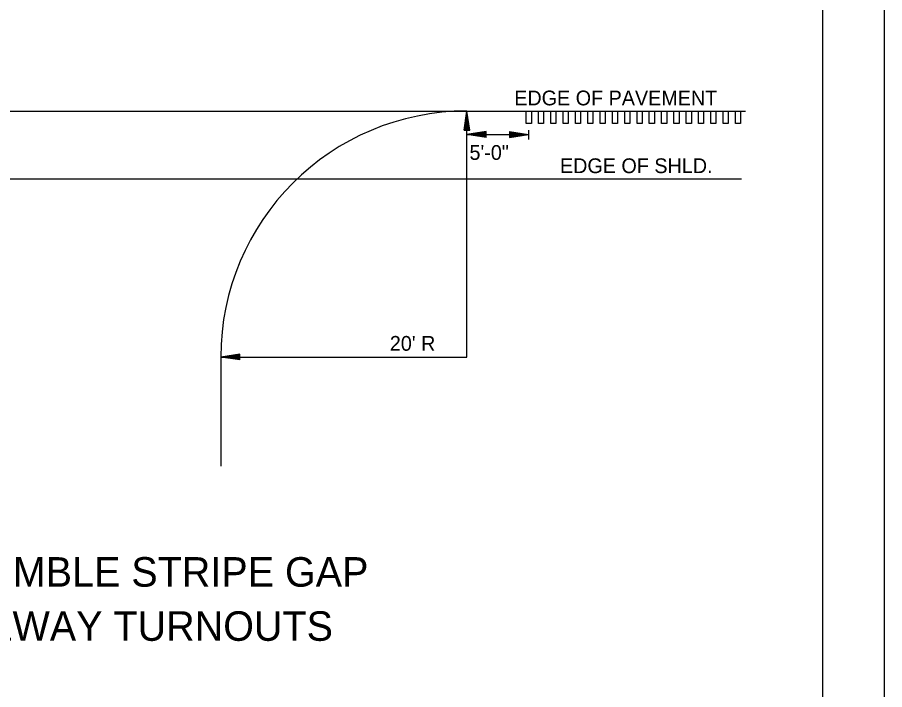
# Model space of a CAD drawing. Extents: x 1371343 to 1373043, y 378740 to 382040.
# Drawn here: x 1372692.4 to 1373042.9, y 380373.5 to 380645.4 of the extents above; entities that cross this region are included whole.
import ezdxf

# ---------------------------------------------------------------- set-up
doc = ezdxf.new("R2010")
doc.units = 0
for name, color, linetype in [('E_Existing ROW', 7, 'Continuous'), ('R_Border Notes', 7, 'Continuous'), ('R_Border PE', 7, 'Continuous')]:
    doc.layers.add(name, color=color, linetype=linetype)

msp = doc.modelspace()

# ---------------------------------------------------------------- linework, layer by layer
at = {"layer": 'E_Existing ROW'}
for points in [[(1371342.92, 379840.49), (1373042.92, 379840.49), (1373042.92, 380940.49), (1371342.92, 380940.49)], [(1371367.92, 379865.49), (1373017.92, 379865.49), (1373017.92, 380915.49), (1371367.92, 380915.49)]]:
    msp.add_lwpolyline(points, close=True, dxfattribs=at)
at = {"layer": 'R_Border Notes'}
for p, q in [((1372475.93, 380607.52), (1372986.72, 380607.52)), ((1372874.12, 380508.02), (1372874.12, 380607.52)), ((1372898.99, 380599.74), (1372898.99, 380596.06)), ((1372874.12, 380598.03), (1372898.99, 380598.03)), ((1372474.28, 380580.11), (1372985.07, 380580.11)), ((1372774.61, 380508.02), (1372774.61, 380463.96)), ((1372774.61, 380508.02), (1372874.12, 380508.02))]:
    msp.add_line(p, q, dxfattribs=at)
for points in [[(1372898.06, 380602.54), (1372898.06, 380607.51), (1372900.13, 380607.51), (1372900.13, 380602.54), (1372898.06, 380602.54)], [(1372903.03, 380602.54), (1372903.03, 380607.51), (1372905.1, 380607.51), (1372905.1, 380602.54), (1372903.03, 380602.54)], [(1372908.01, 380602.54), (1372908.01, 380607.51), (1372910.08, 380607.51), (1372910.08, 380602.54), (1372908.01, 380602.54)], [(1372912.98, 380602.54), (1372912.98, 380607.51), (1372915.05, 380607.51), (1372915.05, 380602.54), (1372912.98, 380602.54)], [(1372917.95, 380602.54), (1372917.95, 380607.51), (1372920.03, 380607.51), (1372920.03, 380602.54), (1372917.95, 380602.54)], [(1372922.93, 380602.54), (1372922.93, 380607.51), (1372925, 380607.51), (1372925, 380602.54), (1372922.93, 380602.54)], [(1372927.9, 380602.54), (1372927.9, 380607.51), (1372929.98, 380607.51), (1372929.98, 380602.54), (1372927.9, 380602.54)], [(1372932.88, 380602.54), (1372932.88, 380607.51), (1372934.95, 380607.51), (1372934.95, 380602.54), (1372932.88, 380602.54)], [(1372937.85, 380602.54), (1372937.85, 380607.51), (1372939.93, 380607.51), (1372939.93, 380602.54), (1372937.85, 380602.54)], [(1372942.83, 380602.54), (1372942.83, 380607.51), (1372944.9, 380607.51), (1372944.9, 380602.54), (1372942.83, 380602.54)], [(1372947.8, 380602.54), (1372947.8, 380607.51), (1372949.88, 380607.51), (1372949.88, 380602.54), (1372947.8, 380602.54)], [(1372952.78, 380602.54), (1372952.78, 380607.51), (1372954.85, 380607.51), (1372954.85, 380602.54), (1372952.78, 380602.54)], [(1372957.75, 380602.54), (1372957.75, 380607.51), (1372959.82, 380607.51), (1372959.82, 380602.54), (1372957.75, 380602.54)], [(1372962.73, 380602.54), (1372962.73, 380607.51), (1372964.8, 380607.51), (1372964.8, 380602.54), (1372962.73, 380602.54)], [(1372967.7, 380602.54), (1372967.7, 380607.51), (1372969.77, 380607.51), (1372969.77, 380602.54), (1372967.7, 380602.54)], [(1372972.68, 380602.54), (1372972.68, 380607.51), (1372974.75, 380607.51), (1372974.75, 380602.54), (1372972.68, 380602.54)], [(1372977.65, 380602.54), (1372977.65, 380607.51), (1372979.72, 380607.51), (1372979.72, 380602.54), (1372977.65, 380602.54)], [(1372982.63, 380602.54), (1372982.63, 380607.51), (1372984.7, 380607.51), (1372984.7, 380602.54), (1372982.63, 380602.54)]]:
    msp.add_lwpolyline(points, dxfattribs=at)
msp.add_arc((1372874.12, 380508.02), 99.51, 90, 180, dxfattribs=at)
at = {"layer": 'R_Border PE'}
for p, q in [((1372872.97, 380599.82), (1372874.12, 380607.52)), ((1372872.97, 380599.82), (1372874.12, 380607.52)), ((1372875.28, 380599.82), (1372874.12, 380607.52)), ((1372875.28, 380599.82), (1372874.12, 380607.52)), ((1372873.16, 380599.82), (1372874.12, 380606.24)), ((1372873.16, 380599.82), (1372874.12, 380606.24)), ((1372873.35, 380599.82), (1372874.12, 380604.91)), ((1372873.35, 380599.82), (1372874.12, 380604.91)), ((1372873.55, 380599.82), (1372874.12, 380603.63)), ((1372873.55, 380599.82), (1372874.12, 380603.63)), ((1372875.08, 380599.82), (1372874.12, 380606.24)), ((1372875.08, 380599.82), (1372874.12, 380606.24)), ((1372874.89, 380599.82), (1372874.12, 380604.91)), ((1372874.89, 380599.82), (1372874.12, 380604.91)), ((1372874.69, 380599.82), (1372874.12, 380603.63)), ((1372874.69, 380599.82), (1372874.12, 380603.63)), ((1372872.97, 380599.82), (1372875.28, 380599.82)), ((1372872.97, 380599.82), (1372875.28, 380599.82)), ((1372873.75, 380599.82), (1372874.12, 380602.32)), ((1372873.75, 380599.82), (1372874.12, 380602.32)), ((1372873.94, 380599.82), (1372874.12, 380601.04)), ((1372873.94, 380599.82), (1372874.12, 380601.04)), ((1372874.5, 380599.82), (1372874.12, 380602.32)), ((1372874.5, 380599.82), (1372874.12, 380602.32)), ((1372874.3, 380599.82), (1372874.12, 380601.04)), ((1372874.3, 380599.82), (1372874.12, 380601.04)), ((1372881.83, 380599.19), (1372874.12, 380598.03)), ((1372881.83, 380596.87), (1372874.12, 380598.03)), ((1372881.83, 380598.99), (1372875.41, 380598.03)), ((1372881.83, 380597.07), (1372875.41, 380598.03)), ((1372881.83, 380598.8), (1372876.73, 380598.03)), ((1372881.83, 380597.26), (1372876.73, 380598.03)), ((1372881.83, 380598.6), (1372878.02, 380598.03)), ((1372881.83, 380597.46), (1372878.02, 380598.03)), ((1372881.83, 380598.41), (1372879.32, 380598.03)), ((1372881.83, 380597.66), (1372879.32, 380598.03)), ((1372881.83, 380598.21), (1372880.61, 380598.03)), ((1372881.83, 380597.85), (1372880.61, 380598.03)), ((1372881.83, 380596.87), (1372881.83, 380599.19)), ((1372891.29, 380599.19), (1372898.99, 380598.03)), ((1372891.29, 380599.19), (1372891.29, 380596.87)), ((1372891.29, 380598.99), (1372897.71, 380598.03)), ((1372891.29, 380598.8), (1372896.38, 380598.03)), ((1372891.29, 380598.6), (1372895.1, 380598.03)), ((1372891.29, 380598.4), (1372893.79, 380598.03)), ((1372891.29, 380598.21), (1372892.51, 380598.03)), ((1372891.29, 380596.87), (1372898.99, 380598.03)), ((1372891.29, 380597.65), (1372893.79, 380598.03)), ((1372891.29, 380597.26), (1372896.38, 380598.03)), ((1372891.29, 380597.07), (1372897.71, 380598.03)), ((1372891.29, 380597.46), (1372895.1, 380598.03)), ((1372891.29, 380597.85), (1372892.51, 380598.03)), ((1372782.32, 380509.17), (1372774.61, 380508.02)), ((1372782.32, 380509.17), (1372774.61, 380508.02)), ((1372782.32, 380508.98), (1372775.9, 380508.02)), ((1372782.32, 380508.98), (1372775.9, 380508.02)), ((1372782.32, 380508.78), (1372777.23, 380508.02)), ((1372782.32, 380508.78), (1372777.23, 380508.02)), ((1372782.32, 380508.59), (1372778.51, 380508.02)), ((1372782.32, 380508.59), (1372778.51, 380508.02)), ((1372782.32, 380508.39), (1372779.81, 380508.02)), ((1372782.32, 380508.39), (1372779.81, 380508.02)), ((1372782.32, 380506.86), (1372782.32, 380509.17)), ((1372782.32, 380506.86), (1372782.32, 380509.17)), ((1372782.32, 380506.86), (1372774.61, 380508.02)), ((1372782.32, 380506.86), (1372774.61, 380508.02)), ((1372782.32, 380507.05), (1372775.9, 380508.02)), ((1372782.32, 380507.05), (1372775.9, 380508.02)), ((1372782.32, 380507.25), (1372777.23, 380508.02)), ((1372782.32, 380507.25), (1372777.23, 380508.02)), ((1372782.32, 380507.44), (1372778.51, 380508.02)), ((1372782.32, 380507.44), (1372778.51, 380508.02)), ((1372782.32, 380507.64), (1372779.81, 380508.02)), ((1372782.32, 380507.64), (1372779.81, 380508.02)), ((1372782.32, 380508.2), (1372781.1, 380508.02)), ((1372782.32, 380508.2), (1372781.1, 380508.02)), ((1372782.32, 380507.84), (1372781.1, 380508.02)), ((1372782.32, 380507.84), (1372781.1, 380508.02))]:
    msp.add_line(p, q, dxfattribs=at)

# ---------------------------------------------------------------- texts
at = {"layer": 'R_Border Notes'}
for s, height, p in [('EDGE OF PAVEMENT', 5.9696, (1372893.21, 380609.82)), ('5\'-0"', 5.97, (1372875.13, 380587.77)), ('EDGE OF SHLD.', 5.9696, (1372911.7, 380582.41)), ("20' R", 5.97, (1372842.94, 380510.58)), ('DETAIL FOR RUMBLE STRIPE GAP', 11.9393, (1372569.02, 380415.18)), ('AT DRIVEWAY TURNOUTS', 11.9393, (1372616.83, 380393.29))]:
    msp.add_text(s, height=height, dxfattribs=at).set_placement(p)

doc.saveas('drawing.dxf')
